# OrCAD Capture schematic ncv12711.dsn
size A; title: NCV12711 - Transient 12 V @ 1 A @ 100 kHz; rev: 0
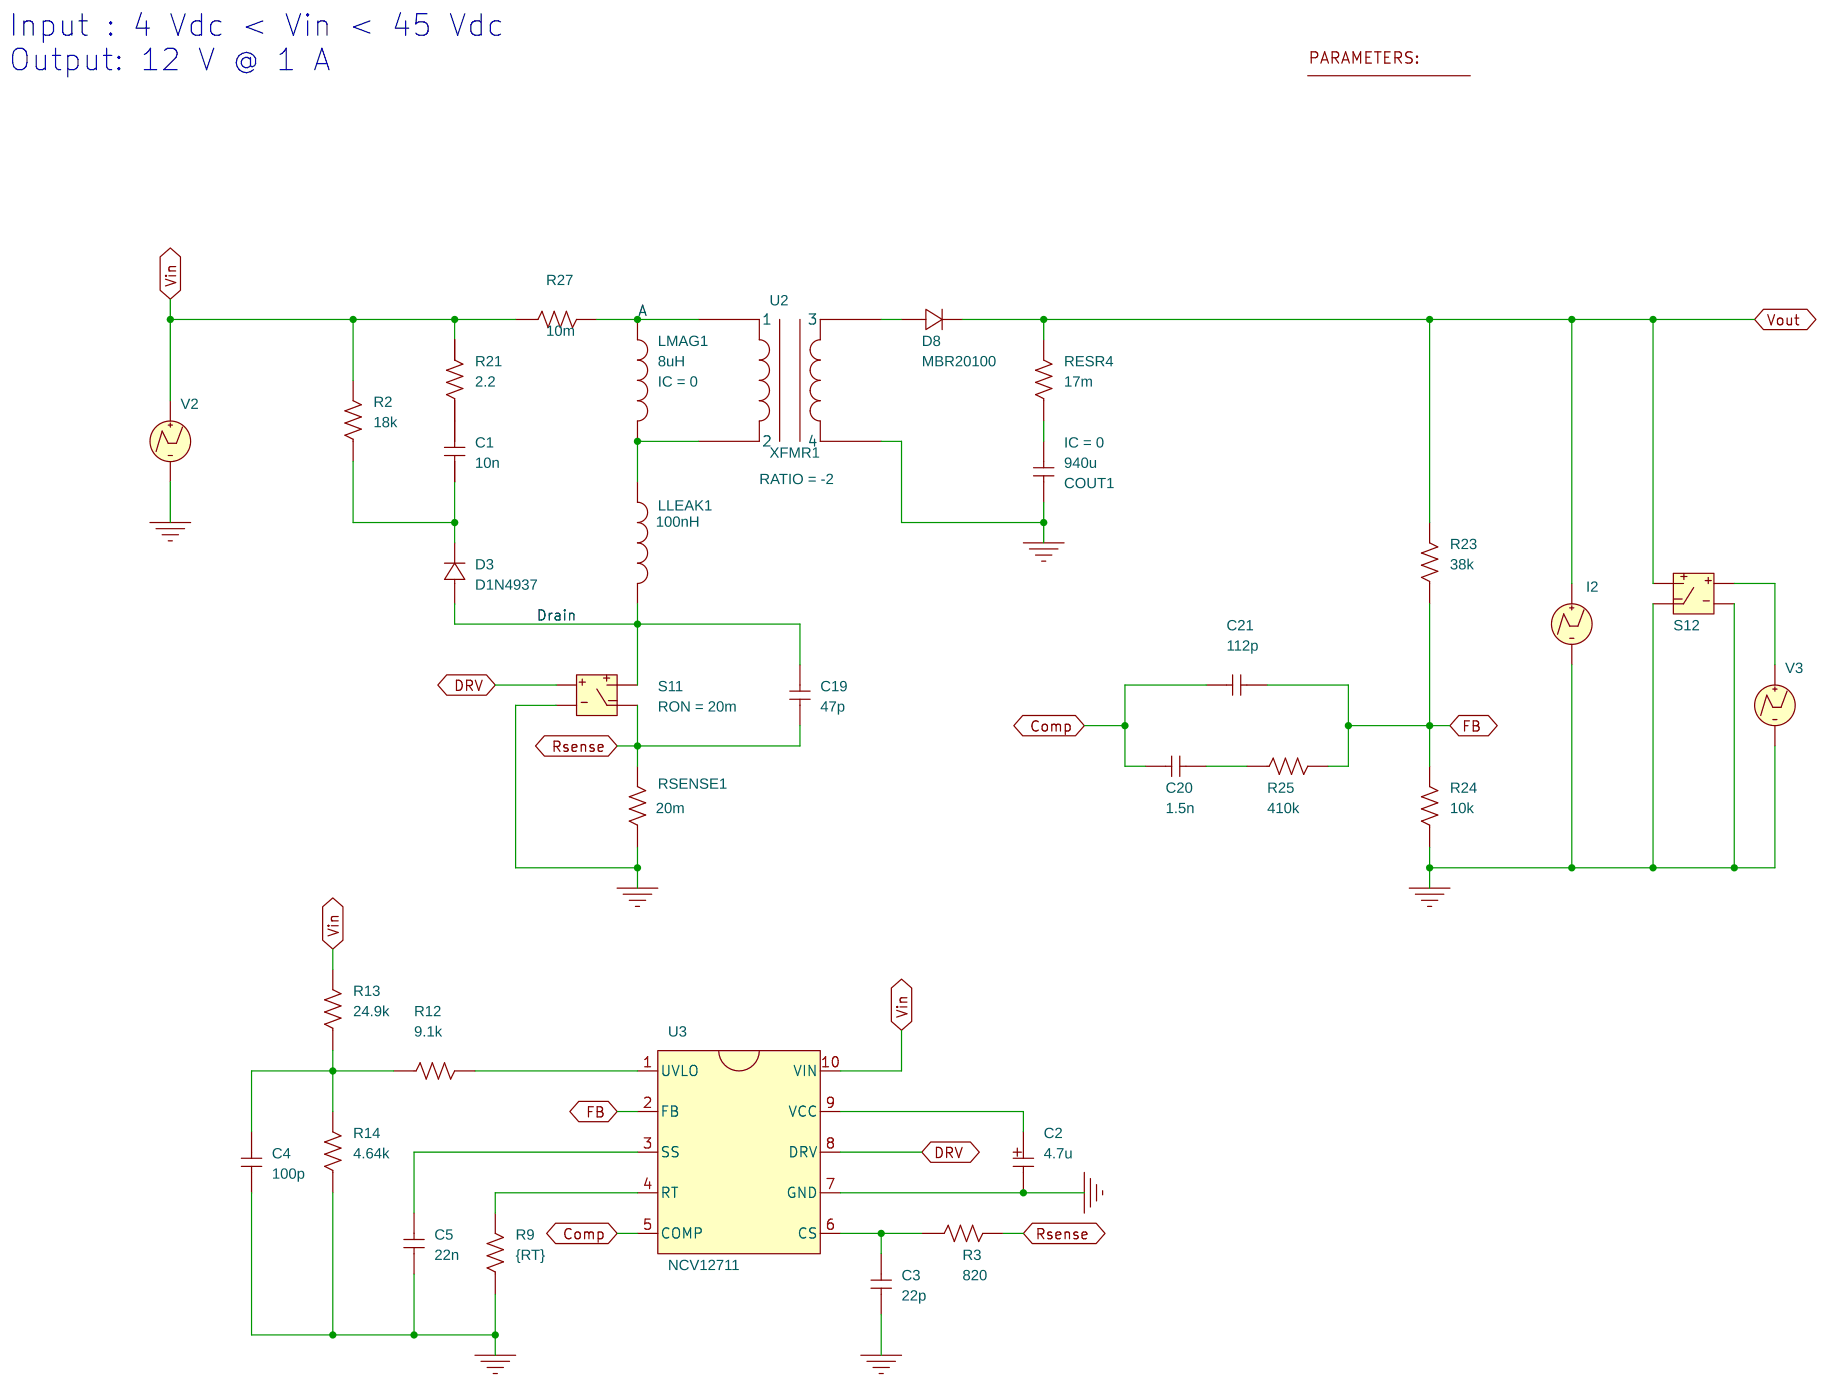
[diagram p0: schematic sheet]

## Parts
1  PARAM
C1  10n  [RAD/CK05]
C2  4.7u  [CPAX575x150031]
C3  22p  [cap196]
C4  100p  [cap196]
C5  22n  [cap196]
C19  47p  [RAD/CK05]
C20  1.5n  [cap196]
C21  112p  [cap196]
COUT1  940u  [CK05]
D3  D1N4937  [DO-41]
D8  MBR20100  [D-67]
I2  IPWL
LLEAK1  100nH  [L2012C]
LMAG1  8uH  [L2012C]
R2  18k  [RC05]
R3  820  [AXRC05]
R9  {RT}  [AXRC05]
R12  9.1k  [AXRC05]
R13  24.9k  [AXRC05]
R14  4.64k  [AXRC05]
R21  2.2  [AXRC05]
R23  38k  [AXRC05]
R24  10k  [AXRC05]
R25  410k  [AXRC05]
R27  10m  [AXRC05]
RESR4  17m  [RC05]
RSENSE1  20m  [RC05]
S11  S
S12  S
U2  XFMR1
U3  NCV12711
V2  VPWL
V3  VPWL

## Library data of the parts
1 = PARAM: Fsw: {(10Meg/(RT+1500)+25)*1k}; GOPP: {((OPP/100)*1m)/3}; OPP: 15; RT: 132k
C1 C3-C5 C19-C21 = C
C2 = C_elect
COUT1 = C: IC: 0
D3 = D1N4937
D8 = MBR20100
I2 = IPWL: I1: 1; I10: 1; I2: 1; I3: 0.2; I4: 0.2; I5: 1; I6: 1; I7: 0.2; I8: 0.2; I9: 1; T1: 0; T10: 40m; T2: 14m; T3: 14.01m; T4: 17m; T5: 17.01m; T6: 30m; T7: 30.01m; T8: 33m; T9: 33.01m
LLEAK1 = L
LMAG1 = L: IC: 0
R2 R3 R9 R12-R14 R21 R23-R25 R27 RESR4 RSENSE1 = R
S11 = S: ROFF: 100e6; RON: 20m; VOFF: 2; VON: 3
S12 = S: ROFF: 100e6; RON: 0.001m; VOFF: 2; VON: 3
U2 = XFMR1: RATIO: -2
U3 = NCV12711
V2 = VPWL: T1: 0; T2: 0.01m; T3: 1m; T4: 20m; T5: 20.001m; T6: 21m; T7: 22m; T8: 40m; V1: 0; V2: 0; V3: 4; V4: 4; V5: 0; V6: 0; V7: 45; V8: 45
V3 = VPWL: T1: 0; T2: 20m; T3: 20.001m; T4: 20.9m; T5: 20.9001m; V1: 0; V2: 0; V3: 10; V4: 10; V5: 0

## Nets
Vin: R2.2 R13.2 R21.2 R27.1 U3.10(VIN) V2.1(+)
0: C2.N(-) C3.1 C4.1 C5.1 COUT1.2 I2.2(-) R9.1 R14.1 R24.1 RSENSE1.1 S11.1(2) S12.1(2) S12.3(4) U2.3(4) U3.7(GND) V2.2(-) V3.2(-)
A: LMAG1.1 R27.2 U2.0(1)
Comp: C20.1 C21.1 U3.5(COMP)
Drain: C19.2 D3.1 LLEAK1.1 S11.2(3)
DRV: S11.0(1) U3.8(DRV)
FB: C21.2 R23.1 R24.2 R25.2 U3.2(FB)
Rsense: C19.1 R3.2 RSENSE1.2 S11.3(4)
Vout: D8.2 I2.1(+) R23.2 RESR4.2 S12.2(3)
N3001709: C2.P(+) U3.9(VCC)
N3002053: C3.2 R3.1 U3.6(CS)
N3008628: R9.2 U3.4(RT)
N3010084: C4.2 R12.1 R13.1 R14.2
N3010112: R12.2 U3.1(UVLO)
N3010316: C5.2 U3.3(SS)
N3013504: D8.1 U2.2(3)
N3013608: COUT1.1 RESR4.1
N3013714: C1.1 D3.2 R2.1
N3013750: LLEAK1.2 LMAG1.2 U2.1(2)
N3068556: C20.2 R25.1
N3075243: C1.2 R21.1
N3113339: S12.0(1) V3.1(+)

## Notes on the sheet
- Input : 4 Vdc < Vin < 45 Vdc
  Output: 12 V @ 1 A
